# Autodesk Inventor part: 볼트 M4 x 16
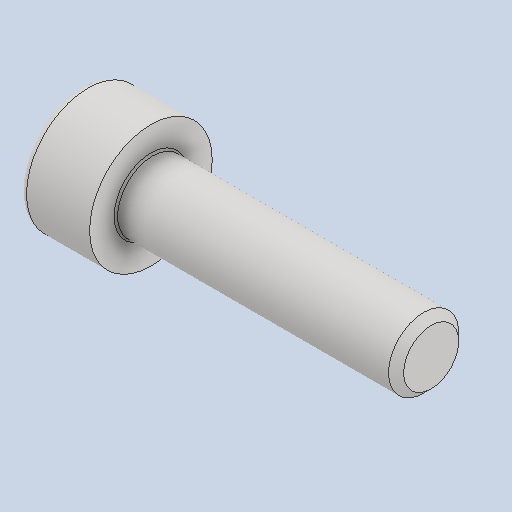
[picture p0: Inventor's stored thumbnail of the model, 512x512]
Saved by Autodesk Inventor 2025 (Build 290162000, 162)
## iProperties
Created: 2025-08
Part Number: 볼트 M4 x 16
Material: 스테인리스강
Description: 6각 소켓 머리 캡 나사
Document SubType Name: Modeling
Designer: infra02
Density: 8.08 g/cm^3
Appearance: 기본값
Author: jhkim
Sending System: Autodesk Inventor 2026
Preprocessor: ST-DEVELOPER v20.1
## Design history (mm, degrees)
feature "Solid1"
node "솔리드1"
